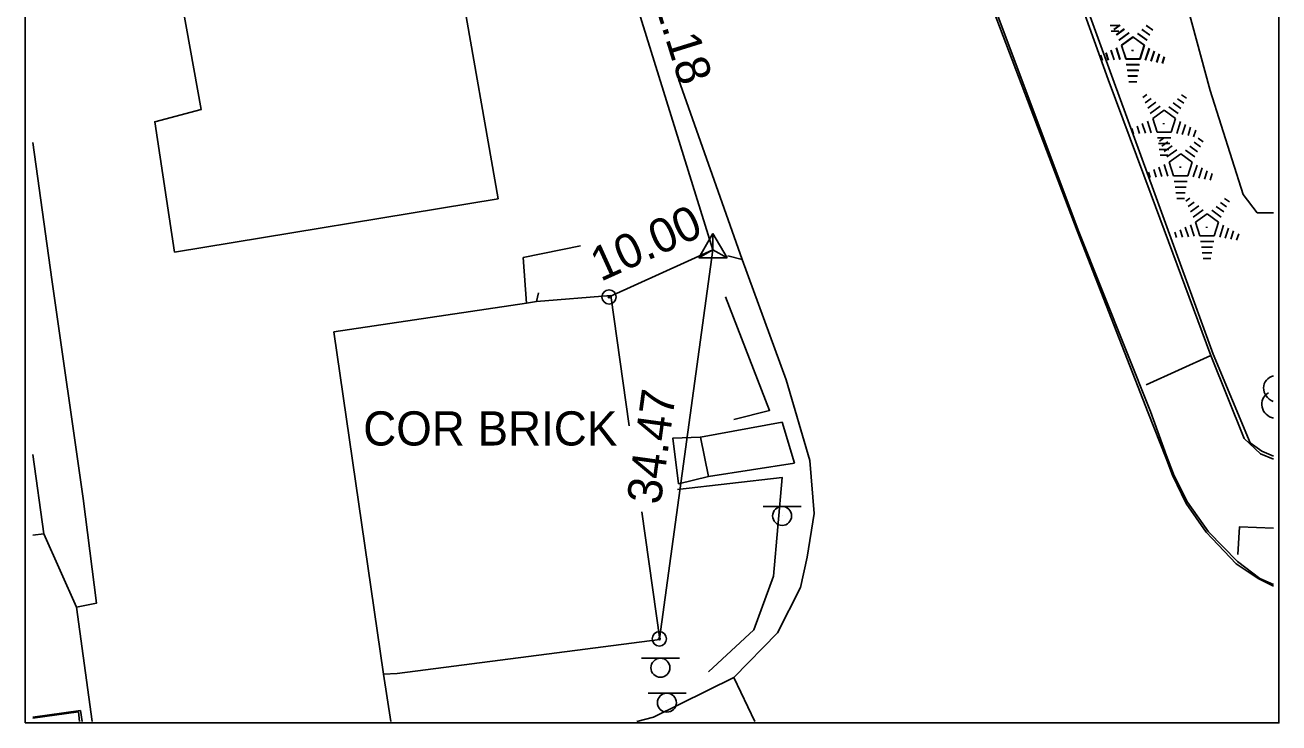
# Model space of a CAD drawing. Extents: x 1586965 to 1590952, y 716317 to 720029.
# Drawn here: x 1590707.2 to 1590817.2, y 716489.9 to 716551.1 of the extents above; entities that cross this region are included whole.
import ezdxf

# ---------------------------------------------------------------- set-up
doc = ezdxf.new("R2010")
doc.units = 0
for name, color, linetype in [('C_C', 7, 'Continuous'), ('CBP', 7, 'Continuous'), ('CPSM', 7, 'Continuous'), ('Default', 7, 'Continuous'), ('LAPB', 7, 'Continuous'), ('LBC', 7, 'Continuous'), ('LBF', 7, 'Continuous'), ('LS', 7, 'Continuous'), ('LTC', 7, 'Continuous'), ('LTD', 7, 'Continuous'), ('LW', 7, 'Continuous'), ('LWS', 7, 'Continuous'), ('NBL2', 7, 'Continuous'), ('PET', 7, 'Continuous'), ('RC', 7, 'Continuous'), ('RDP', 7, 'Continuous'), ('RSW', 7, 'Continuous'), ('SSGN', 7, 'Continuous')]:
    doc.layers.add(name, color=color, linetype=linetype)

msp = doc.modelspace()

# ---------------------------------------------------------------- linework, layer by layer
at = {"layer": 'CBP'}
for centre, radius in [((1590758.43, 716527.25), 0.625), ((1590758.43, 716527.25), 0.0833), ((1590762.84, 716497.24), 0.625), ((1590762.84, 716497.24), 0.0833)]:
    msp.add_circle(centre, radius, dxfattribs=at)
at = {"layer": 'CPSM'}
for p, q in [((1590766.29, 716530.67), (1590767.54, 716532.83)), ((1590768.79, 716530.67), (1590767.54, 716532.83)), ((1590767.54, 716531.39), (1590767.54, 716532.83)), ((1590766.29, 716530.67), (1590767.54, 716531.39)), ((1590767.54, 716531.39), (1590767.54, 716531.39)), ((1590767.54, 716531.39), (1590768.79, 716530.67)), ((1590766.29, 716530.67), (1590768.79, 716530.67))]:
    msp.add_line(p, q, dxfattribs=at)
at = {"layer": 'Default'}
for p, q in [((1590755.32, 716570.71), (1590767.54, 716531.39)), ((1590767.54, 716531.39), (1590758.43, 716527.25)), ((1590767.54, 716531.39), (1590762.84, 716497.24))]:
    msp.add_line(p, q, dxfattribs=at)
at = {"layer": 'LAPB'}
for points in [[(1590752.24, 716527.61), (1590752.06, 716526.86)], [(1590769.36, 716516.49), (1590772.51, 716517.29), (1590768.65, 716527.27)], [(1590767.16, 716494.36), (1590771.13, 716498.03), (1590772.85, 716502.73), (1590773.61, 716511.41), (1590764.44, 716510.34)]]:
    msp.add_lwpolyline(points, dxfattribs=at)
at = {"layer": 'LBC'}
for points in [[(1590734.27, 716524.19), (1590751.18, 716526.71), (1590752.06, 716526.86), (1590758.57, 716527.38)], [(1590760.2, 716515.95), (1590758.57, 716527.38)], [(1590734.27, 716524.19), (1590738.64, 716494.15), (1590739.83, 716494.21), (1590762.89, 716497.2), (1590761.29, 716508.38)], [(1590707.88, 716506.35), (1590708.84, 716506.47), (1590707.88, 716513.41)]]:
    msp.add_lwpolyline(points, dxfattribs=at)
at = {"layer": 'LBF'}
msp.add_lwpolyline([(1590767.16, 716511.49), (1590764.52, 716510.86), (1590764.02, 716514.85), (1590766.44, 716514.95)], dxfattribs=at)
at = {"layer": 'LS'}
for points in [[(1590707.88, 716490.28), (1590711.87, 716490.84)], [(1590711.98, 716489.99), (1590711.87, 716490.84)]]:
    msp.add_lwpolyline(points, dxfattribs=at)
at = {"layer": 'LTC'}
for p, q in [((1590803.23, 716551.07), (1590802.39, 716551.07)), ((1590802.72, 716550.72), (1590803.25, 716551.1)), ((1590802.75, 716550.71), (1590803.28, 716551.09)), ((1590805.54, 716551.08), (1590806.09, 716550.68)), ((1590805.57, 716551.07), (1590806.12, 716550.67)), ((1590803.14, 716550.57), (1590802.47, 716550.57)), ((1590802.93, 716550.25), (1590803.63, 716550.77)), ((1590802.96, 716550.24), (1590803.66, 716550.76)), ((1590803.14, 716549.79), (1590804.02, 716550.43)), ((1590803.17, 716549.78), (1590804.05, 716550.42)), ((1590803.37, 716549.33), (1590804.38, 716550.07)), ((1590803.39, 716549.32), (1590804.4, 716550.06)), ((1590804.38, 716550.07), (1590805.37, 716549.34)), ((1590804.4, 716550.06), (1590805.4, 716549.33)), ((1590804.8, 716550.38), (1590805.61, 716549.79)), ((1590804.82, 716550.37), (1590805.63, 716549.78)), ((1590805.17, 716550.73), (1590805.85, 716550.24)), ((1590805.19, 716550.72), (1590805.87, 716550.23)), ((1590802.46, 716548.9), (1590802.73, 716548.06)), ((1590802.48, 716548.89), (1590802.75, 716548.05)), ((1590802.91, 716549.11), (1590803.24, 716548.1)), ((1590802.94, 716549.1), (1590803.27, 716548.08)), ((1590803.37, 716549.33), (1590803.75, 716548.14)), ((1590803.39, 716549.32), (1590803.78, 716548.13)), ((1590805.37, 716549.34), (1590804.98, 716548.14)), ((1590805.4, 716549.33), (1590805.01, 716548.13)), ((1590805.81, 716549.07), (1590805.47, 716548.03)), ((1590805.84, 716549.06), (1590805.5, 716548.02)), ((1590806.26, 716548.82), (1590805.97, 716547.94)), ((1590806.28, 716548.81), (1590806, 716547.93)), ((1590801.54, 716548.47), (1590801.7, 716548)), ((1590801.57, 716548.45), (1590801.72, 716547.99)), ((1590802, 716548.68), (1590802.21, 716548.03)), ((1590802.03, 716548.67), (1590802.24, 716548.02)), ((1590804.98, 716548.14), (1590803.75, 716548.14)), ((1590805.01, 716548.13), (1590803.78, 716548.13)), ((1590806.7, 716548.57), (1590806.46, 716547.84)), ((1590806.73, 716548.56), (1590806.49, 716547.83)), ((1590807.14, 716548.32), (1590806.96, 716547.75)), ((1590807.17, 716548.31), (1590806.98, 716547.74)), ((1590804.94, 716547.64), (1590803.8, 716547.64)), ((1590804.97, 716547.63), (1590803.83, 716547.63)), ((1590804.86, 716547.14), (1590803.87, 716547.14)), ((1590804.89, 716547.13), (1590803.9, 716547.13)), ((1590804.78, 716546.64), (1590803.95, 716546.64)), ((1590804.8, 716546.63), (1590803.97, 716546.63)), ((1590804.69, 716546.14), (1590804.02, 716546.14)), ((1590804.72, 716546.13), (1590804.04, 716546.13)), ((1590805.26, 716544.75), (1590805.62, 716545.01)), ((1590805.47, 716544.28), (1590806, 716544.67)), ((1590808.29, 716544.64), (1590808.84, 716544.24)), ((1590808.66, 716544.99), (1590809.08, 716544.69)), ((1590805.68, 716543.82), (1590806.39, 716544.33)), ((1590805.89, 716543.35), (1590806.77, 716543.99)), ((1590806.12, 716542.9), (1590807.13, 716543.63)), ((1590807.13, 716543.63), (1590808.13, 716542.91)), ((1590807.55, 716543.94), (1590808.36, 716543.36)), ((1590807.92, 716544.29), (1590808.6, 716543.8)), ((1590804.75, 716542.25), (1590804.96, 716541.59)), ((1590805.21, 716542.46), (1590805.48, 716541.63)), ((1590805.66, 716542.68), (1590805.99, 716541.66)), ((1590806.12, 716542.9), (1590806.5, 716541.7)), ((1590808.13, 716542.91), (1590807.73, 716541.7)), ((1590808.56, 716542.64), (1590808.23, 716541.6)), ((1590809.01, 716542.39), (1590808.72, 716541.5)), ((1590804.3, 716542.03), (1590804.45, 716541.56)), ((1590807.73, 716541.7), (1590806.5, 716541.7)), ((1590807.7, 716541.2), (1590806.55, 716541.2)), ((1590806.72, 716540.93), (1590807.07, 716541.19)), ((1590809.45, 716542.14), (1590809.22, 716541.41)), ((1590809.9, 716541.89), (1590809.71, 716541.31)), ((1590810.12, 716541.17), (1590810.54, 716540.87)), ((1590807.61, 716540.7), (1590806.62, 716540.7)), ((1590807.53, 716540.2), (1590806.7, 716540.2)), ((1590806.93, 716540.47), (1590807.46, 716540.85)), ((1590807.14, 716540), (1590807.84, 716540.51)), ((1590807.35, 716539.53), (1590808.23, 716540.17)), ((1590809, 716540.13), (1590809.81, 716539.54)), ((1590809.38, 716540.47), (1590810.05, 716539.98)), ((1590809.75, 716540.82), (1590810.3, 716540.42)), ((1590807.45, 716539.7), (1590806.77, 716539.7)), ((1590807.57, 716539.08), (1590808.58, 716539.81)), ((1590807.57, 716539.08), (1590807.96, 716537.89)), ((1590808.58, 716539.81), (1590809.58, 716539.09)), ((1590809.58, 716539.09), (1590809.19, 716537.89)), ((1590805.75, 716538.21), (1590805.9, 716537.74)), ((1590806.21, 716538.43), (1590806.42, 716537.77)), ((1590806.66, 716538.64), (1590806.93, 716537.81)), ((1590807.12, 716538.86), (1590807.45, 716537.84)), ((1590809.19, 716537.89), (1590807.96, 716537.89)), ((1590810.02, 716538.82), (1590809.68, 716537.78)), ((1590810.46, 716538.57), (1590810.18, 716537.68)), ((1590810.91, 716538.32), (1590810.67, 716537.59)), ((1590811.35, 716538.07), (1590811.17, 716537.49)), ((1590809.15, 716537.39), (1590808.01, 716537.39)), ((1590809.07, 716536.89), (1590808.08, 716536.89)), ((1590808.98, 716536.39), (1590808.15, 716536.39)), ((1590808.9, 716535.89), (1590808.23, 716535.89)), ((1590809.03, 716535.66), (1590809.39, 716535.91)), ((1590812.43, 716535.9), (1590812.85, 716535.59)), ((1590809.24, 716535.19), (1590809.77, 716535.58)), ((1590809.45, 716534.73), (1590810.16, 716535.24)), ((1590809.66, 716534.26), (1590810.54, 716534.9)), ((1590809.89, 716533.8), (1590810.9, 716534.54)), ((1590810.9, 716534.54), (1590811.9, 716533.81)), ((1590811.32, 716534.85), (1590812.13, 716534.26)), ((1590811.69, 716535.2), (1590812.37, 716534.71)), ((1590812.06, 716535.55), (1590812.61, 716535.15)), ((1590809.43, 716533.59), (1590809.76, 716532.57)), ((1590809.89, 716533.8), (1590810.27, 716532.61)), ((1590811.9, 716533.81), (1590811.5, 716532.61)), ((1590812.33, 716533.54), (1590812, 716532.5)), ((1590808.07, 716532.94), (1590808.22, 716532.47)), ((1590808.52, 716533.15), (1590808.73, 716532.5)), ((1590808.98, 716533.37), (1590809.25, 716532.53)), ((1590811.5, 716532.61), (1590810.27, 716532.61)), ((1590812.78, 716533.29), (1590812.49, 716532.41)), ((1590813.22, 716533.04), (1590812.99, 716532.31)), ((1590813.67, 716532.79), (1590813.48, 716532.22)), ((1590811.47, 716532.11), (1590810.32, 716532.11)), ((1590811.38, 716531.61), (1590810.39, 716531.61)), ((1590811.3, 716531.11), (1590810.47, 716531.11)), ((1590811.22, 716530.61), (1590810.54, 716530.61))]:
    msp.add_line(p, q, dxfattribs=at)
at = {"layer": 'LTD'}
for centre, major_axis, ratio, start_param, end_param in [((1590817.14, 716519.16), (1.21, -0.51), 0.895232, 2.262639, 4.712389), ((1590816.85, 716517.79), (0.58, -1.04), 0.959034, 3.141593, 5.643771)]:
    msp.add_ellipse(centre, major_axis=major_axis, ratio=ratio, start_param=start_param, end_param=end_param, dxfattribs=at)
at = {"layer": 'LW'}
msp.add_lwpolyline([(1590816.72, 716513.27), (1590815.7, 716513.71), (1590814.67, 716514.44), (1590811.44, 716522.23), (1590806.32, 716536.3), (1590802.62, 716546.4), (1590795.37, 716566.37), (1590792.94, 716574.53), (1590791.51, 716580.57)], dxfattribs=at)
at = {"layer": 'LWS'}
msp.add_lwpolyline([(1590803.38, 716580.57), (1590805.28, 716567.09), (1590811.16, 716545.37), (1590814.07, 716536.23), (1590815.3, 716534.63), (1590816.72, 716534.63)], dxfattribs=at)
at = {"layer": 'NBL2'}
msp.add_lwpolyline([(1590707.19, 716489.86), (1590817.19, 716489.86), (1590817.19, 716605.86), (1590707.19, 716605.86)], close=True, dxfattribs=at)
at = {"layer": 'PET'}
for points in [[(1590816.72, 716501.87), (1590815.38, 716502.54), (1590813.44, 716503.83), (1590810.82, 716506.6), (1590809.07, 716509.13), (1590807.86, 716511.61), (1590807.26, 716513.17), (1590805.73, 716517.09), (1590799.48, 716533.06), (1590789.21, 716560.16), (1590781.44, 716580.57)], [(1590771.23, 716489.99), (1590769.38, 716493.86), (1590773.21, 716497.77), (1590775.22, 716501.75), (1590775.8, 716504.42), (1590776.42, 716508.25), (1590776.03, 716512.89), (1590773.97, 716519.97), (1590770.1, 716530.53), (1590764.52, 716546.36)]]:
    msp.add_lwpolyline(points, dxfattribs=at)
at = {"layer": 'RC'}
msp.add_lwpolyline([(1590816.72, 716502.02), (1590815.53, 716502.54), (1590813.56, 716504.04), (1590811.02, 716506.63), (1590809.18, 716509.24), (1590808, 716511.55), (1590807.33, 716513.31), (1590805.92, 716517.2), (1590799.59, 716533.11), (1590789.46, 716560.15), (1590781.65, 716580.57)], dxfattribs=at)
at = {"layer": 'RDP'}
for points in [[(1590716.01, 716580.57), (1590722.65, 716543.71), (1590718.57, 716542.63), (1590720.31, 716531.18), (1590748.7, 716535.86)], [(1590740.82, 716580.57), (1590745.38, 716554.72), (1590748.7, 716535.86)], [(1590755.91, 716531.73), (1590750.9, 716530.7), (1590751.18, 716526.71)], [(1590770.1, 716530.53), (1590768.84, 716530.86)], [(1590713.08, 716489.99), (1590711.71, 716500.03), (1590708.84, 716506.47)], [(1590739.27, 716489.99), (1590738.64, 716494.15)], [(1590707.88, 716490.37), (1590712.07, 716490.95)], [(1590712.19, 716489.99), (1590712.07, 716490.95)]]:
    msp.add_lwpolyline(points, dxfattribs=at)
at = {"layer": 'RSW'}
for points in [[(1590805.54, 716519.53), (1590811.23, 716522.1), (1590806, 716536.21), (1590802.2, 716546.34), (1590795.11, 716566.17), (1590792.7, 716574.61), (1590791.27, 716580.57)], [(1590711.71, 716500.03), (1590713.47, 716500.38), (1590712.29, 716509.55), (1590709.53, 716528.78), (1590707.88, 716540.81)], [(1590816.72, 716513), (1590815.58, 716513.47), (1590814.16, 716514.82), (1590811.23, 716522.1)], [(1590774.69, 716512.66), (1590767.16, 716511.49), (1590766.44, 716514.95), (1590773.61, 716516.27)], [(1590774.69, 716512.66), (1590773.61, 716516.27)], [(1590816.72, 716506.95), (1590813.75, 716507.08), (1590813.59, 716504.65)], [(1590760.87, 716489.99), (1590762.32, 716490.38), (1590769.38, 716493.86)]]:
    msp.add_lwpolyline(points, dxfattribs=at)
at = {"layer": 'SSGN'}
for p, q in [((1590771.96, 716508.86), (1590775.29, 716508.86)), ((1590773.61, 716508.03), (1590773.61, 716508.03)), ((1590761.28, 716495.54), (1590764.62, 716495.54)), ((1590762.93, 716494.71), (1590762.93, 716494.71)), ((1590761.85, 716492.47), (1590765.19, 716492.47)), ((1590763.5, 716491.64), (1590763.5, 716491.64))]:
    msp.add_line(p, q, dxfattribs=at)
for centre in [(1590773.61, 716508.03), (1590762.93, 716494.71), (1590763.5, 716491.64)]:
    msp.add_circle(centre, 0.833, dxfattribs=at)

# ---------------------------------------------------------------- texts
at = {"layer": 'C_C'}
msp.add_text('COR BRICK', height=3, dxfattribs=at).set_placement((1590736.86, 716514.21))
at = {"layer": 'Default'}
for s, rotation, p in [('41.18', 287.2596, (1590761.7, 716555.24)), ('10.00', 24.414, (1590757.69, 716528.56)), ('34.47', 82.1679, (1590762.94, 716508.95))]:
    msp.add_text(s, height=3, rotation=rotation, dxfattribs=at).set_placement(p)
at = {"layer": 'LTC'}
for p in [(1590804.26, 716549.08), (1590804.29, 716549.07), (1590807.01, 716542.65), (1590808.47, 716538.83), (1590810.78, 716533.55)]:
    msp.add_text('.', height=1.04, rotation=270, dxfattribs=at).set_placement(p)

doc.saveas('drawing.dxf')
